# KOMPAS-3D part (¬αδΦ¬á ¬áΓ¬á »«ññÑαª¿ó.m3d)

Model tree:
1. Эскиз:1
2. Операция выдавливания:1
     Расстояние 1 = 0.5; Расстояние 2 = 1
3. Эскиз:2
4. Операция выдавливания:2
     Расстояние 1 = 0.2; Расстояние 2 = 1
5. Эскиз:3
6. Операция выдавливания:3
     Расстояние 1 = 0.2; Расстояние 2 = 1
7. Эскиз:4
8. Операция выдавливания:4
     Расстояние 1 = 0.3; Расстояние 2 = 1
9. Скругление:1
     Радиус = 0.1
10. Эскиз:5
11. Операция выдавливания:5
     Расстояние 1 = 0.3; Расстояние 2 = 1
12. Массив по концентрической сетке:1  (with: Операция выдавливания:5)  (labels: Экземпляр ( 1, 1 ); Экземпляр ( 1, 2 ); Экземпляр ( 1, 3 ); Экземпляр ( 1, 4 ))
     N 2 = 10; Шаг 2 = 360
13. Эскиз:7
14. Вырезать элемент выдавливания:1
     Расстояние 1 = 0.2
15. Эскиз:8
16. Операция выдавливания:6
     Расстояние 1 = 0.2; Расстояние 2 = 1

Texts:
  крышка катка поддержив
  Сплав АЛ8  ГОСТ 1583-93
  Номер 1
  Номер 2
